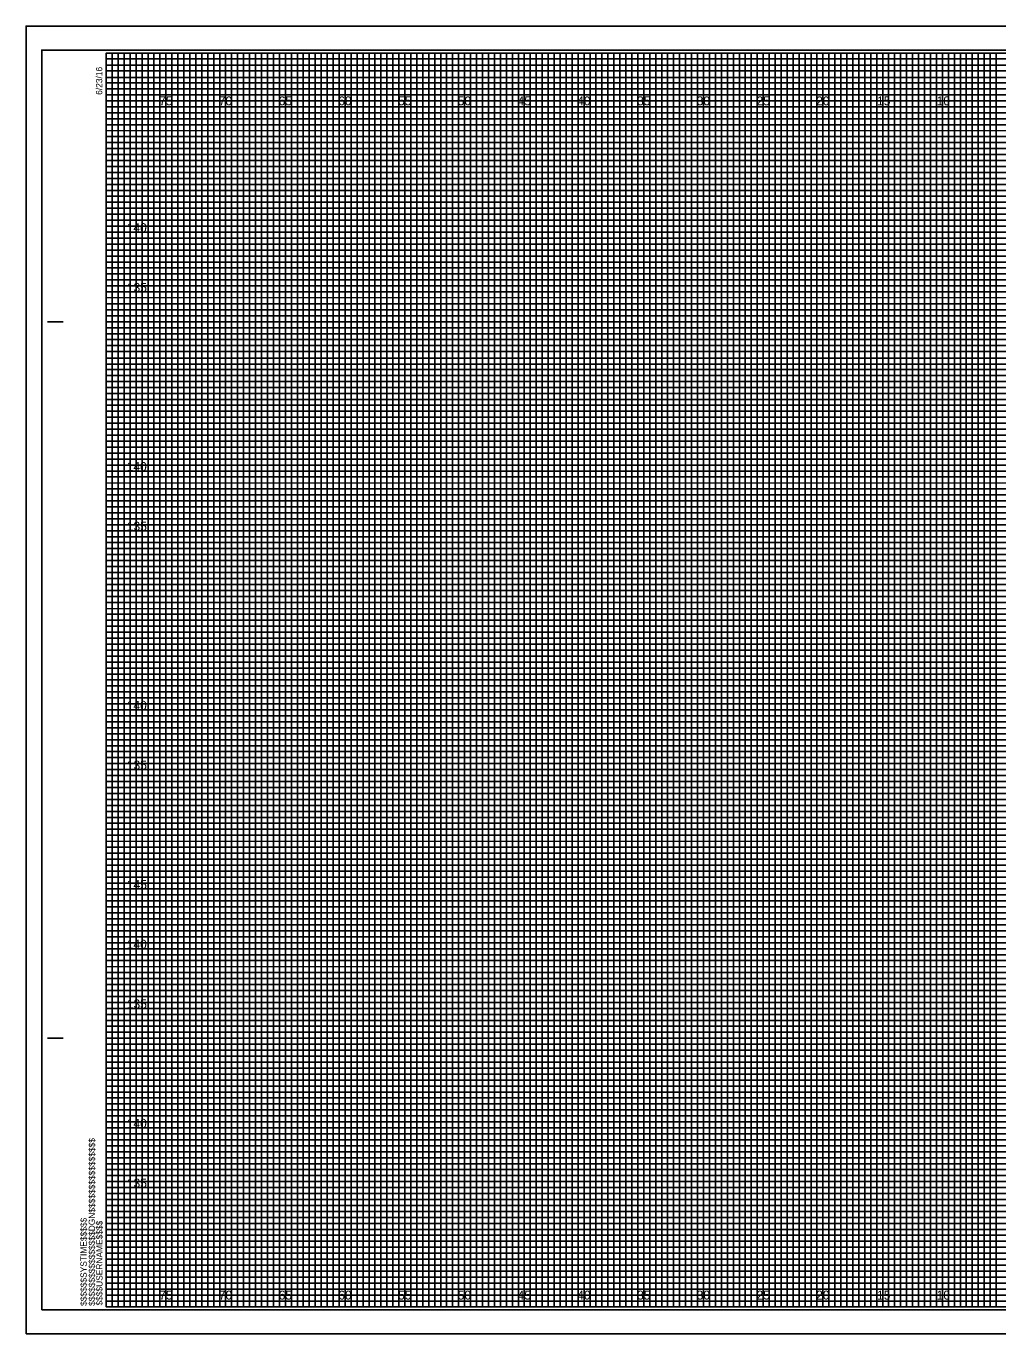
# Model space of a CAD drawing. Extents: x -7 to 162, y -2 to 107.
# Drawn here: x -6.7 to 74.6, y -2.3 to 107.3 of the extents above; entities that cross this region are included whole.
import ezdxf

# ---------------------------------------------------------------- set-up
doc = ezdxf.new("R2010")
doc.units = 0
for name, color, linetype in [('Prop CMT Conc Surface', 7, 'Continuous'), ('Prop CMT Concrete Structures', 7, 'Continuous'), ('Prop CMT Pvmt Course 1', 7, 'Continuous'), ('Prop CMT Pvmt Surface Shoulder', 7, 'Continuous'), ('Prop CMT Pvmt Wedge Surface 2', 7, 'Continuous'), ('Prop CMT Pvmt Wedge Surface 3', 7, 'Continuous'), ('Prop XS Ditch Standard Text', 7, 'Continuous'), ('Prop XS Hydro Elevations', 7, 'Continuous'), ('Prop XS Retaining Wall', 7, 'Continuous'), ('Prop XS SE Text', 7, 'Continuous'), ('Prop XS Side Slope Text', 7, 'Continuous')]:
    doc.layers.add(name, color=color, linetype=linetype)

msp = doc.modelspace()

# ---------------------------------------------------------------- linework, layer by layer
at = {"layer": 'Prop CMT Conc Surface'}
for p, q in [((-4.9, 82.5), (-3.65, 82.5)), ((-4.85, 82.5), (-3.6, 82.5)), ((-4.9, 22.5), (-3.65, 22.5)), ((-4.85, 22.5), (-3.6, 22.5)), ((0, 0), (0, 0)), ((0, 0), (0, 0)), ((0, 0), (0, 0)), ((0, 0), (0, 0)), ((0, 0), (0, 0)), ((0, 0), (0, 0)), ((0, 0), (0, 0))]:
    msp.add_line(p, q, dxfattribs=at)
msp.add_lwpolyline([(160, 105), (0, 105), (0, 0), (160, 0)], close=True, dxfattribs=at)
at = {"layer": 'Prop CMT Concrete Structures'}
for points in [[(0, 0), (0.5, 0), (0.5, 105), (1, 105), (1, 0)], [(1, 0), (1.5, 0), (1.5, 105), (2, 105), (2, 0)], [(2.5, 0), (3, 0), (3, 105), (3.5, 105), (3.5, 0)], [(3.5, 0), (4, 0), (4, 105), (4.5, 105), (4.5, 0)], [(5, 0), (5.5, 0), (5.5, 105), (6, 105), (6, 0)], [(6, 0), (6.5, 0), (6.5, 105), (7, 105), (7, 0)], [(7.5, 0), (8, 0), (8, 105), (8.5, 105), (8.5, 0)], [(8.5, 0), (9, 0), (9, 105), (9.5, 105), (9.5, 0)], [(10, 0), (10.5, 0), (10.5, 105), (11, 105), (11, 0)], [(11, 0), (11.5, 0), (11.5, 105), (12, 105), (12, 0)], [(12.5, 0), (13, 0), (13, 105), (13.5, 105), (13.5, 0)], [(13.5, 0), (14, 0), (14, 105), (14.5, 105), (14.5, 0)], [(15, 0), (15.5, 0), (15.5, 105), (16, 105), (16, 0)], [(16, 0), (16.5, 0), (16.5, 105), (17, 105), (17, 0)], [(17.5, 0), (18, 0), (18, 105), (18.5, 105), (18.5, 0)], [(18.5, 0), (19, 0), (19, 105), (19.5, 105), (19.5, 0)], [(20, 0), (20.5, 0), (20.5, 105), (21, 105), (21, 0)], [(21, 0), (21.5, 0), (21.5, 105), (22, 105), (22, 0)], [(22.5, 0), (23, 0), (23, 105), (23.5, 105), (23.5, 0)], [(23.5, 0), (24, 0), (24, 105), (24.5, 105), (24.5, 0)], [(25, 0), (25.5, 0), (25.5, 105), (26, 105), (26, 0)], [(26, 0), (26.5, 0), (26.5, 105), (27, 105), (27, 0)], [(27.5, 0), (28, 0), (28, 105), (28.5, 105), (28.5, 0)], [(28.5, 0), (29, 0), (29, 105), (29.5, 105), (29.5, 0)], [(30, 0), (30.5, 0), (30.5, 105), (31, 105), (31, 0)], [(31, 0), (31.5, 0), (31.5, 105), (32, 105), (32, 0)], [(32.5, 0), (33, 0), (33, 105), (33.5, 105), (33.5, 0)], [(33.5, 0), (34, 0), (34, 105), (34.5, 105), (34.5, 0)], [(35, 0), (35.5, 0), (35.5, 105), (36, 105), (36, 0)], [(36, 0), (36.5, 0), (36.5, 105), (37, 105), (37, 0)], [(37.5, 0), (38, 0), (38, 105), (38.5, 105), (38.5, 0)], [(38.5, 0), (39, 0), (39, 105), (39.5, 105), (39.5, 0)], [(40, 0), (40.5, 0), (40.5, 105), (41, 105), (41, 0)], [(41, 0), (41.5, 0), (41.5, 105), (42, 105), (42, 0)], [(42.5, 0), (43, 0), (43, 105), (43.5, 105), (43.5, 0)], [(43.5, 0), (44, 0), (44, 105), (44.5, 105), (44.5, 0)], [(45, 0), (45.5, 0), (45.5, 105), (46, 105), (46, 0)], [(46, 0), (46.5, 0), (46.5, 105), (47, 105), (47, 0)], [(47.5, 0), (48, 0), (48, 105), (48.5, 105), (48.5, 0)], [(48.5, 0), (49, 0), (49, 105), (49.5, 105), (49.5, 0)], [(50, 0), (50.5, 0), (50.5, 105), (51, 105), (51, 0)], [(51, 0), (51.5, 0), (51.5, 105), (52, 105), (52, 0)], [(52.5, 0), (53, 0), (53, 105), (53.5, 105), (53.5, 0)], [(53.5, 0), (54, 0), (54, 105), (54.5, 105), (54.5, 0)], [(55, 0), (55.5, 0), (55.5, 105), (56, 105), (56, 0)], [(56, 0), (56.5, 0), (56.5, 105), (57, 105), (57, 0)], [(57.5, 0), (58, 0), (58, 105), (58.5, 105), (58.5, 0)], [(58.5, 0), (59, 0), (59, 105), (59.5, 105), (59.5, 0)], [(60, 0), (60.5, 0), (60.5, 105), (61, 105), (61, 0)], [(61, 0), (61.5, 0), (61.5, 105), (62, 105), (62, 0)], [(62.5, 0), (63, 0), (63, 105), (63.5, 105), (63.5, 0)], [(63.5, 0), (64, 0), (64, 105), (64.5, 105), (64.5, 0)], [(65, 0), (65.5, 0), (65.5, 105), (66, 105), (66, 0)], [(66, 0), (66.5, 0), (66.5, 105), (67, 105), (67, 0)], [(67.5, 0), (68, 0), (68, 105), (68.5, 105), (68.5, 0)], [(68.5, 0), (69, 0), (69, 105), (69.5, 105), (69.5, 0)], [(70, 0), (70.5, 0), (70.5, 105), (71, 105), (71, 0)], [(71, 0), (71.5, 0), (71.5, 105), (72, 105), (72, 0)], [(72.5, 0), (73, 0), (73, 105), (73.5, 105), (73.5, 0)], [(73.5, 0), (74, 0), (74, 105), (74.5, 105), (74.5, 0)]]:
    msp.add_lwpolyline(points, dxfattribs=at)
at = {"layer": 'Prop CMT Pvmt Course 1'}
for p, q in [((0, 104.5), (130, 104.5)), ((130, 103.99), (0, 103.99)), ((0, 103.99), (0, 103.5)), ((0, 103.5), (130, 103.5)), ((130, 102.95), (0, 102.95)), ((0, 102.95), (0, 102)), ((0, 102), (160, 102))]:
    msp.add_line(p, q, dxfattribs=at)
for points in [[(0, 101.5), (135, 101.5), (160, 101.5), (160, 101), (0, 101)], [(0, 100.5), (160, 100.5), (160, 99.5), (0, 99.5)], [(0, 99), (160, 99), (160, 98.5), (0, 98.49)], [(0, 98), (160, 98), (160, 97), (0, 97)], [(0, 96.5), (160, 96.5), (160, 96), (0, 96)], [(0, 95.5), (160, 95.5), (160, 94.5), (0, 94.5)], [(0, 94), (160, 94), (160, 93.5), (0, 93.5)], [(0, 93), (160, 93), (160, 92), (0, 92)], [(0, 91.5), (160, 91.5), (160, 91), (0, 91)], [(0, 90.5), (160, 90.5), (160, 89.5), (0, 89.5)], [(0, 89), (160, 89), (160, 88.5), (0, 88.5)], [(0, 88), (160, 88), (160, 86.98), (160, 86.5), (160, 86), (0, 86)], [(0, 87), (160, 87), (160, 86.5), (0, 86.5)], [(0, 85.5), (160, 85.5), (160, 84.5), (0, 84.52)], [(0, 84.52), (160, 84.5), (160, 84), (0, 84)], [(0, 83.5), (160, 83.5), (160, 83), (0, 83)], [(0, 82), (160, 82), (160, 81.5), (0, 81.5)], [(0, 81), (160, 81), (160, 80.5), (0, 80.5)], [(-0.04, 79.45), (160, 79.45), (160, 78.94), (-0.04, 78.94)], [(0, 78.5), (160, 78.5), (160, 78), (0, 78)], [(0, 77), (160, 77), (160, 76.5), (0, 76.5)], [(0, 76), (160, 76), (160, 75.5), (0, 75.5)], [(0, 74.5), (160, 74.5), (160, 74), (0, 74)], [(0, 73.5), (160, 73.5), (160, 73), (0, 73)], [(0, 72), (160, 72), (160, 71.5), (0, 71.5)], [(0, 71), (160, 71), (160, 70.5), (0, 70.5)], [(0, 69.5), (160, 69.5), (160, 68.99), (0, 69)], [(0, 68.5), (160, 68.5), (160, 68), (0, 68)], [(0, 67), (160, 67), (160, 66.5), (0, 66.5)], [(0, 66), (160, 66), (160, 65.5), (0, 65.5)], [(0, 64.5), (160, 64.5), (160, 64), (0, 64)], [(0, 63.5), (160, 63.5), (160, 63), (0, 63)], [(0, 62), (160, 62), (160, 61.5), (0, 61.5)], [(0, 61), (160, 61), (160, 60.5), (0, 60.5)], [(0, 59.5), (160, 59.5), (160, 59), (0, 59)], [(0, 58.5), (160.03, 58.45), (160, 58), (0, 58)], [(0, 57), (160, 57), (160, 56.5), (0, 56.5)], [(0, 56), (160, 56), (160, 55.5), (0, 55.5)], [(0, 54.5), (160, 54.5), (160, 54), (0, 54)], [(0, 53.5), (160, 53.5), (160, 53), (0, 53)], [(0, 52), (160, 52), (160, 51.5), (0, 51.5)], [(0, 51), (160, 51), (160, 50.5), (0, 50.5)], [(0, 49.5), (160, 49.5), (160, 49), (0, 49)], [(0, 48.5), (160, 48.5), (160, 48), (0, 48)], [(0, 47), (160, 47), (160, 46.5), (0, 46.5)], [(0, 46), (160, 46), (160, 45.5), (0, 45.5)], [(0, 44.5), (160, 44.5), (160, 44), (0, 44)], [(0, 43.5), (160, 43.5), (160, 43), (0, 43)], [(0, 42), (160, 42), (160, 41.5), (0, 41.5)], [(0, 41), (160, 41), (160, 40.5), (0, 40.5)], [(0, 39.5), (160, 39.5), (160, 38.99), (0, 39)], [(0, 38.5), (160, 38.5), (160, 38), (0, 38)], [(0, 37), (160, 37), (160, 36.5), (0, 36.5)], [(0, 36), (160, 36), (160, 35.5), (0, 35.5)], [(0, 34.5), (160, 34.5), (160, 34), (0, 34)], [(0, 33.5), (160, 33.5), (160, 33), (0, 33)], [(0, 32), (160, 32), (160, 31.5), (0, 31.5)], [(0, 31), (160, 31), (160, 30.5), (0, 30.5)], [(0, 29.5), (160, 29.5), (160, 29), (0, 29)], [(0, 28.5), (160.03, 28.46), (160, 28), (0, 28)], [(0, 27), (160, 27), (160, 26.5), (0, 26.5)], [(0, 26), (160, 26), (160, 25.5), (0, 25.5)], [(0, 24.5), (160, 24.5), (160, 24), (0, 24)], [(0, 23.5), (160, 23.5), (160, 23), (0, 23)], [(0, 22), (160, 22), (160, 21.5), (0, 21.5)], [(0, 21), (160, 21), (160, 20.5), (0, 20.5)], [(0, 19.5), (160, 19.5), (160, 19), (0, 19)], [(0, 18.5), (160, 18.5), (160, 18), (0, 18)], [(0, 17), (160, 17), (160, 16.5), (0, 16.5)], [(0, 16), (160, 16), (160, 15.5), (0, 15.5)], [(0, 14.5), (160, 14.5), (160, 14), (0, 14)], [(0, 13.5), (160, 13.5), (160, 13), (0, 13)], [(0, 12), (160, 12), (160, 11.5), (0, 11.5)], [(0, 11), (160, 11), (160, 10.5), (0, 10.5)], [(0, 9.5), (160, 9.5), (160, 9), (0, 9)], [(0, 8.5), (160, 8.5), (160, 8), (0, 8)], [(0, 7), (160, 7), (160, 6.5), (0, 6.5)], [(0, 6), (160, 6), (160, 5.5), (0, 5.5)], [(0, 4.5), (160, 4.5), (160, 4), (0, 4)], [(0, 3.5), (160, 3.5), (160, 3), (0, 3)], [(0, 2), (160, 2), (160, 1.5), (0, 1.5)], [(0, 1), (160, 1), (160, 0.5), (0, 0.5)]]:
    msp.add_lwpolyline(points, dxfattribs=at)
at = {"layer": 'Prop CMT Pvmt Surface Shoulder'}
for points in [[(0, 105), (2.5, 105), (2.5, 0), (7.5, 0), (7.5, 105), (12.5, 105), (12.5, 0), (17.5, 0), (17.5, 105), (22.5, 105), (22.5, 0), (27.5, 0), (27.5, 105), (32.5, 105), (32.5, 0), (37.5, 0), (37.5, 105), (42.5, 105), (42.5, 0), (47.5, 0), (47.5, 105), (52.5, 105), (52.5, 0), (57.5, 0), (57.5, 105), (62.5, 105), (62.5, 0), (67.5, 0), (67.5, 105), (72.5, 105), (72.5, 0), (77.5, 0)], [(0, 102.5), (137.5, 102.5)], [(0, 92.5), (160, 92.5), (160, 97.5), (0, 97.5)], [(0, 82.5), (160, 82.5), (160, 87.5), (0, 87.5)], [(0, 72.5), (160, 72.5), (160, 77.5), (0, 77.5)], [(0, 62.5), (160, 62.5), (160, 67.5), (0, 67.5)], [(0, 52.5), (160, 52.5), (160, 57.5), (0, 57.5)], [(0, 42.5), (160, 42.5), (160, 47.5), (0, 47.5)], [(0, 32.5), (160, 32.5), (160, 37.5), (0, 37.5)], [(0, 22.5), (160, 22.5), (160, 27.5), (0, 27.5)], [(0, 12.5), (160, 12.5), (160, 17.5), (0, 17.5)], [(0, 2.5), (160, 2.5), (160, 7.5), (0, 7.5)]]:
    msp.add_lwpolyline(points, dxfattribs=at)
at = {"layer": 'Prop CMT Pvmt Wedge Surface 3'}
for p, q in [((5, 105), (0, 105)), ((5, 0), (5, 105)), ((15, 105), (10, 105)), ((10, 105), (10, 0)), ((15, 0), (15, 105)), ((25, 105), (20, 105)), ((20, 105), (20, 0)), ((25, 0), (25, 105)), ((35, 105), (30, 105)), ((30, 105), (30, 0)), ((35, 0), (35, 105)), ((45, 105), (40, 105)), ((40, 105), (40, 0)), ((45, 0), (45, 105)), ((55, 105), (50, 105)), ((50, 105), (50, 0)), ((55, 0), (55, 105)), ((65, 105), (60, 105)), ((60, 105), (60, 0)), ((65, 0), (65, 105)), ((75, 105), (70, 105)), ((70, 105), (70, 0)), ((10, 0), (5, 0)), ((20, 0), (15, 0)), ((30, 0), (25, 0)), ((40, 0), (35, 0)), ((50, 0), (45, 0)), ((60, 0), (55, 0)), ((70, 0), (65, 0))]:
    msp.add_line(p, q, dxfattribs=at)
for points in [[(0, 100), (160, 100), (160, 95), (0, 95)], [(0, 90), (160, 90), (160, 85), (0, 85)], [(0, 80), (160, 80), (160, 75), (0, 75)], [(0, 70), (160, 70), (160, 65), (0, 65)], [(0, 60), (160, 60), (160, 55), (0, 55)], [(0, 50), (160, 50), (160, 45), (0, 45)], [(0, 40), (160, 40), (160, 35), (0, 35)], [(0, 30), (160, 30), (160, 25), (0, 25)], [(0, 20), (160, 20), (160, 15), (0, 15)], [(0, 10), (160, 10), (160, 5), (0, 5)]]:
    msp.add_lwpolyline(points, dxfattribs=at)
at = {"layer": 'Prop XS Ditch Standard Text'}
for p, q in [((5, 0), (5, 105)), ((10, 0), (10, 105)), ((15, 0), (15, 105)), ((20, 0), (20, 105)), ((25, 0), (25, 105)), ((30, 0), (30, 105)), ((35, 0), (35, 105)), ((40, 0), (40, 105)), ((45, 0), (45, 105)), ((50, 0), (50, 105)), ((55, 0), (55, 105)), ((60, 0), (60, 105)), ((65, 0), (65, 105)), ((70, 0), (70, 105)), ((0, 100), (160, 100)), ((0, 95), (160, 95)), ((0, 90), (160, 90)), ((0, 85), (160, 85)), ((0, 80), (160, 80)), ((0, 75), (160, 75)), ((0, 70), (160, 70)), ((0, 65), (160, 65)), ((0, 60), (160, 60)), ((0, 55), (160, 55)), ((0, 50), (160, 50)), ((0, 45), (160, 45)), ((0, 40), (160, 40)), ((0, 35), (160, 35)), ((0, 30), (160, 30)), ((0, 25), (160, 25)), ((0, 20), (160, 20)), ((0, 15), (160, 15)), ((0, 10), (160, 10)), ((0, 5), (160, 5))]:
    msp.add_line(p, q, dxfattribs=at)
at = {"layer": 'Prop XS Hydro Elevations'}
for p, q in [((161.65, 107.25), (-6.7, 107.25)), ((-6.7, 107.25), (-6.7, -2.25)), ((-6.7, -2.25), (161.65, -2.25))]:
    msp.add_line(p, q, dxfattribs=at)
at = {"layer": 'Prop XS SE Text'}
msp.add_lwpolyline([(-5.4, -0.25), (161.2, -0.25), (161.2, 105.25), (-5.4, 105.25)], close=True, dxfattribs=at)
at = {"layer": 'Prop XS Side Slope Text'}
msp.add_lwpolyline([(-6.7, -2.25), (161.65, -2.25), (161.65, 107.25), (-6.7, 107.25)], close=True, dxfattribs=at)

# ---------------------------------------------------------------- texts
at = {"layer": 'Prop CMT Conc Surface'}
for s, p in [('6/23/16', (-0.33, 101.5)), ('$$$$$$$$$$$$$$$$DGN$$$$$$$$$$$$$$$$', (-0.94, 0.09)), ('$$$$$$SYSTIME$$$$$', (-1.63, 0.09)), ('$$$$USERNAME$$$$', (-0.31, 0.12))]:
    msp.add_text(s, height=0.525, rotation=90, dxfattribs=at).set_placement(p)
at = {"layer": 'Prop CMT Pvmt Wedge Surface 2'}
for s, p in [('75', (4.44, 100.62)), ('70', (9.43, 100.62)), ('65', (14.44, 100.62)), ('60', (19.43, 100.62)), ('55', (24.44, 100.62)), ('50', (29.43, 100.62)), ('45', (34.44, 100.62)), ('40', (39.43, 100.62)), ('35', (44.44, 100.62)), ('30', (49.43, 100.62)), ('25', (54.44, 100.62)), ('20', (59.43, 100.62)), ('15', (64.53, 100.62)), ('10', (69.52, 100.62)), ('75', (4.44, 0.62)), ('70', (9.43, 0.62)), ('65', (14.44, 0.62)), ('60', (19.43, 0.62)), ('55', (24.44, 0.62)), ('50', (29.43, 0.62)), ('45', (34.44, 0.62)), ('40', (39.43, 0.62)), ('35', (44.44, 0.62)), ('30', (49.43, 0.62)), ('25', (54.44, 0.62)), ('20', (59.43, 0.62)), ('15', (64.53, 0.62)), ('10', (69.52, 0.62))]:
    msp.add_text(s, height=0.75, dxfattribs=at).set_placement(p)
at = {"layer": 'Prop XS Retaining Wall'}
for s, p in [('140', (1.72, 90)), ('135', (1.73, 85)), ('140', (1.72, 70)), ('135', (1.73, 65)), ('140', (1.72, 50)), ('135', (1.73, 45)), ('145', (1.73, 35)), ('140', (1.72, 30)), ('135', (1.73, 25)), ('140', (1.72, 15)), ('135', (1.73, 10))]:
    msp.add_text(s, height=0.75, dxfattribs=at).set_placement(p)

doc.saveas('drawing.dxf')
